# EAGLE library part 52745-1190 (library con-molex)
FFC/FPC-to-Board 0.50mm (.020") SMT Top Contact Right Angle, ZIF, Style Receptacle 52745 / 52435 Source: http://www.molex.com/product/ffc/52745.html
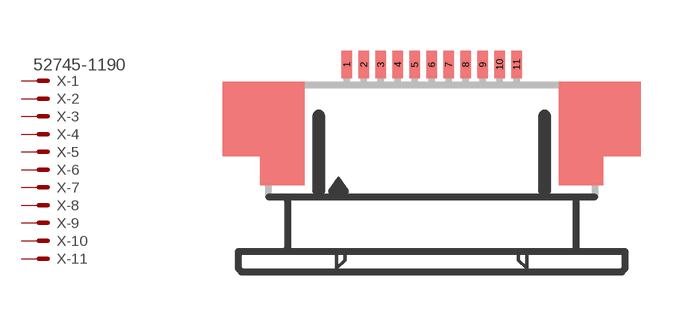
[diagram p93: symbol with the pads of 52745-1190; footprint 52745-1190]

Designator prefix X; gates -1=MV -2=M -3=M -4=M -5=M -6=M -7=M -8=M -9=M -10=M -11=M

## 52745-1190 (OC_FARNELL: unknown; OC_NEWARK: unknown)  [52745-1190]
1  -1:S  pas
2  -2:S  pas
3  -3:S  pas
4  -4:S  pas
5  -5:S  pas
6  -6:S  pas
7  -7:S  pas
8  -8:S  pas
9  -9:S  pas
10  -10:S  pas
11  -11:S  pas

## Footprint 52745-1190 (pad centres in mm)
FFC/FPC-to-Board 0.50mm (.020") SMT Top Contact Right Angle, ZIF, Style Receptacle 52745 / 52435 Source: http://www.molex.com/product/ffc/52745.html
smd 0.3 x 0.8: 1 -2.5,2.5; 2 -2,2.5; 3 -1.5,2.5; 4 -1,2.5; 5 -0.5,2.5; 6 0,2.5; 7 0.5,2.5; 8 1,2.5; 9 1.5,2.5; 10 2,2.5; 11 2.5,2.5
